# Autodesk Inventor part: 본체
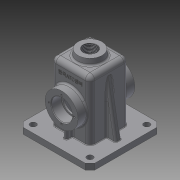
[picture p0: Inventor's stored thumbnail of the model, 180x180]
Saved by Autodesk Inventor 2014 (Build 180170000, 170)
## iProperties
Created: 2017-08
Part Number: 본체
Material: 일반
Document SubType Name: Modeling
Designer: user
Density: 1 g/cm^3
Appearance: 기본값
Author: user
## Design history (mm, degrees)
sketch "스케치1"
  geometry: L1 (-32.5, -32.5)-(32.5, -32.5); L2 (32.5, -32.5)-(32.5, 32.5); L3 (32.5, 32.5)-(-32.5, 32.5); L4 (-32.5, 32.5)-(-32.5, -32.5); L5 (-32.5, -32.5)-(32.5, 32.5); L6 (32.5, -32.5)-(-32.5, 32.5); 1 further point
  constraints: 12 end point, 2 midpoint, 2 parallel, 1 horizontal, 1 perpendicular
  dimensions: "d0" = 65 distance of L2.end L3.end; "d1" = 65 distance of L1.end L2.end
extrude "돌출1" new body sketch "스케치1" distance "d2" = 55; taper "d4" = 0 deg; dims "d3" = 55, "d5" = 0
feature "쉘1" dims "d6" = 5
sketch "스케치2"
  geometry: C1 r 27.5 at (32.5, -55); 1 further point
  constraints: 1 centre point, 1 coincident
  dimensions: "d7" = 55 diameter of C1
extrude "돌출2" join sketch "스케치2" distance "d8" = 15; taper "d9" = 0 deg
fillet "모깎기1" dims "d10" = 8
fillet "모깎기2" dims "d11" = 8
hole "구멍1" diameter "d14" = 30; stored, may be unused: countersink angle "d18" = 90 deg, drill point angle "d20" = 118 deg; dims "d12" = 10, "d13" = 10, "d15" = 6, "d16" = 35, "d17" = 17, "d19" = 8
fillet "모깎기3" dims "d21" = 3
fillet "모깎기4" dims "d22" = 3
sketch "스케치3"
  geometry: L1 (-32.5, 24.5)-(-32.5, -24.5) reference; L2 (-24.5, -32.5)-(24.5, -32.5) reference; L3 (32.5, -24.5)-(32.5, 24.5) reference; L4 (24.5, 32.5)-(-24.5, 32.5) reference; L5 (-60, 60)-(60, 60); L6 (60, 60)-(60, -60); L7 (60, -60)-(-60, -60); L8 (-60, -60)-(-60, 60); L9 (-60, 60)-(60, -60); L10 (60, 60)-(-60, -60); A1 r 8 centre (-24.5, 24.5) between (-24.5, 32.5) and (-32.5, 24.5) reference; A2 r 8 centre (-24.5, -24.5) between (-32.5, -24.5) and (-24.5, -32.5) reference; A3 r 8 centre (24.5, -24.5) between (24.5, -32.5) and (32.5, -24.5) reference; A4 r 8 centre (24.5, 24.5) between (32.5, 24.5) and (24.5, 32.5) reference; 1 further point
  constraints: 12 end point, 2 midpoint, 2 parallel, 1 horizontal, 1 perpendicular
  dimensions: "d23" = 120 distance of L5.start L5.end; "d24" = 120 distance of L7.end L5.start
extrude "돌출3" join sketch "스케치3" distance "d25" = 10; taper "d26" = 0 deg
node "작업 평면1"
sketch "스케치4"
  geometry: C1 r 20 at (0, 0); 1 further point
  constraints: 1 centre point, 1 coincident
  dimensions: "d28" = 40 diameter of C1
extrude "돌출4" join sketch "스케치4" stored distance "d29" = 10; taper "d30" = 0 deg
feature "면 기울기1" dims angle "d31" = 7 deg
hole "구멍2" diameter "d34" = 22.835; stored, may be unused: countersink angle "d38" = 90 deg, drill point angle "d40" = 118 deg; dims "d32" = 10, "d33" = 10, "d35" = 30, "d36" = 35, "d37" = 17, "d39" = 8
sketch "스케치5" dims "d41" = 42
  geometry: C1 r 17.5 at (0, 0) reference; C2 r 27.5 at (0, 0) reference; 2 further points
  constraints: 2 vertical alignment, 1 coincident, 2 other
hole "구멍3" sketch "스케치5" at (0, 21) diameter "d42" = 3.242; stored, may be unused: countersink angle "d46" = 90 deg, drill point angle "d48" = 118 deg; dims "d43" = 8, "d44" = 35, "d45" = 17, "d47" = 10
sketch "스케치6"
  geometry: L1 (60, -60)-(60, 60) reference; L2 (-47.5, -47.5)-(47.5, -47.5); 4 further points
  constraints: 2 coincident, 2 end point, 1 midpoint, 1 perpendicular, 1 vertical alignment
  dimensions: "d52" = 95 distance of L2.start L2.end; "d53" = 47.5 distance of point (0, 0) point (0, -47.5)
hole "구멍4" sketch "스케치6" at (-47.5, -47.5), (47.5, -47.5) diameter "d54" = 10; stored, may be unused: countersink angle "d58" = 90 deg, drill point angle "d60" = 118 deg; dims "d55" = 8, "d56" = 35, "d57" = 17, "d59" = 10
chamfer "모따기1" distance "d61" = 8; stored, may be unused: second distance "d62" = 2, angle "d63" = 45 deg
fillet "모깎기5" dims "d64" = 3
chamfer "모따기2" distance "d65" = 1; stored, may be unused: second distance "d66" = 2, angle "d67" = 45 deg
fillet "모깎기6" dims "d68" = 0.3
sketch "스케치7"
  geometry: L1 (-11.418, 65)-(-11.418, 50) reference; L2 (-11.418, 50)-(-24.5, 50) reference; L3 (-27.5, 47)-(-27.5, -55) reference; L4 (-27.5, -55)-(-60, -55) reference; L5 (-60, -55)-(-60, -45) reference; L6 (-60, -45)-(-32.5, -45) reference; L7 (-32.5, -45)-(-32.5, 47) reference; L8 (-24.5, 55)-(-23.882, 55) reference; L9 (-20.904, 57.634)-(-20, 65) reference; L10 (-20, 65)-(-11.418, 65) reference; L11 (11.418, 50)-(11.418, 65) reference; L12 (11.418, 65)-(20, 65) reference; L13 (20, 65)-(20.904, 57.634) reference; L14 (23.882, 55)-(24.5, 55) reference; L15 (32.5, 47)-(32.5, -45) reference; L16 (32.5, -45)-(60, -45) reference; L17 (60, -45)-(60, -55) reference; L18 (60, -55)-(27.5, -55) reference; L19 (27.5, -55)-(27.5, 47) reference; L20 (24.5, 50)-(11.418, 50) reference; L21 (-48, -45)-(-32.5, 42.905); A1 r 3 centre (-24.5, 47) between (-24.5, 50) and (-27.5, 47) reference; A2 r 8 centre (-24.5, 47) between (-24.5, 55) and (-32.5, 47) reference; A3 r 3 centre (-23.882, 58) between (-23.882, 55) and (-20.904, 57.634) reference; A4 r 3 centre (23.882, 58) between (20.904, 57.634) and (23.882, 55) reference; A5 r 8 centre (24.5, 47) between (32.5, 47) and (24.5, 55) reference; A6 r 3 centre (24.5, 47) between (27.5, 47) and (24.5, 50) reference; 1 further point
  constraints: 2 end point, 2 point on line
  dimensions: "d69" = 12 distance from line of L5 L21.start; "d70" = 100 deg angle of L6 L21
feature "리브1" sketch "스케치7" dims "d71" = 1, "d72" = 10, "d73" = 0, "d74" = 0, "d75" = 1, "d76" = 1
fillet "모깎기7" dims "d77" = 3
fillet "모깎기8" dims "d78" = 3
sketch "스케치8"
  geometry: L1 (-37.5, -22.621)-(-36.526, -21) reference; L2 (-36.526, -21)-(-37.5, -19.379) reference; L3 (-37.5, -19.379)-(-47.5, -19.379) reference; L4 (-47.5, -19.379)-(-47.5, -18.5) reference; L5 (-47.5, -18.5)-(-46.5, -17.5) reference; L6 (-46.5, -17.5)-(-30.8, -17.5) reference; L7 (-30.5, -17.2)-(-30.5, -15) reference; L8 (-30.5, -15)-(-27.5, -15) reference; L9 (-27.5, -15)-(-27.5, -55) reference; L10 (-27.5, -55)-(-60, -55) reference; L11 (-60, -55)-(-60, -45) reference; L12 (-60, -45)-(-32.5, -45) reference; L13 (-32.5, -45)-(-32.5, -30.5) reference; L14 (-35.5, -27.5)-(-47.5, -27.5) reference; L15 (-47.5, -27.5)-(-47.5, -22.621) reference; L16 (-47.5, -22.621)-(-37.5, -22.621) reference; L17 (32.5, -30.5)-(32.5, -45) reference; L18 (32.5, -45)-(60, -45) reference; L19 (60, -45)-(60, -55) reference; L20 (60, -55)-(27.5, -55) reference; L21 (27.5, -55)-(27.5, -15) reference; L22 (27.5, -15)-(30.5, -15) reference; L23 (30.5, -15)-(30.5, -17.2) reference; L24 (30.8, -17.5)-(46.5, -17.5) reference; L25 (46.5, -17.5)-(47.5, -18.5) reference; L26 (47.5, -18.5)-(47.5, -19.379) reference; L27 (47.5, -19.379)-(37.5, -19.379) reference; L28 (37.5, -19.379)-(36.526, -21) reference; L29 (36.526, -21)-(37.5, -22.621) reference; L30 (37.5, -22.621)-(47.5, -22.621) reference; L31 (47.5, -22.621)-(47.5, -27.5) reference; L32 (47.5, -27.5)-(35.5, -27.5) reference; L33 (35.5, 27.5)-(47.5, 27.5) reference; L34 (47.5, 27.5)-(47.5, 22.621) reference; L35 (47.5, 22.621)-(37.5, 22.621) reference; L36 (37.5, 22.621)-(36.526, 21) reference; L37 (36.526, 21)-(37.5, 19.379) reference; L38 (37.5, 19.379)-(47.5, 19.379) reference; L39 (47.5, 19.379)-(47.5, 18.5) reference; L40 (47.5, 18.5)-(46.5, 17.5) reference; L41 (46.5, 17.5)-(30.8, 17.5) reference; L42 (30.5, 17.2)-(30.5, 15) reference; L43 (30.5, 15)-(27.5, 15) reference; L44 (27.5, 15)-(27.5, 47) reference; L45 (24.5, 50)-(11.418, 50) reference; L46 (11.418, 50)-(11.418, 65) reference; L47 (11.418, 65)-(20, 65) reference; L48 (20, 65)-(20.904, 57.634) reference; L49 (23.882, 55)-(24.5, 55) reference; L50 (32.5, 47)-(32.5, 30.5) reference; L51 (-32.5, 30.5)-(-32.5, 47) reference; L52 (-24.5, 55)-(-23.882, 55) reference; L53 (-20.904, 57.634)-(-20, 65) reference; L54 (-20, 65)-(-11.418, 65) reference; L55 (-11.418, 65)-(-11.418, 50) reference; L56 (-11.418, 50)-(-24.5, 50) reference; L57 (-27.5, 47)-(-27.5, 15) reference; L58 (-27.5, 15)-(-30.5, 15) reference; L59 (-30.5, 15)-(-30.5, 17.2) reference; L60 (-30.8, 17.5)-(-46.5, 17.5) reference; L61 (-46.5, 17.5)-(-47.5, 18.5) reference; L62 (-47.5, 18.5)-(-47.5, 19.379) reference; L63 (-47.5, 19.379)-(-37.5, 19.379) reference; L64 (-37.5, 19.379)-(-36.526, 21) reference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; A1 r 0.3 centre (-30.8, -17.2) between (-30.8, -17.5) and (-30.5, -17.2) reference; A2 r 3 centre (-35.5, -30.5) between (-32.5, -30.5) and (-35.5, -27.5) reference; A3 r 3 centre (35.5, -30.5) between (35.5, -27.5) and (32.5, -30.5) reference; A4 r 0.3 centre (30.8, -17.2) between (30.5, -17.2) and (30.8, -17.5) reference; A5 r 3 centre (35.5, 30.5) between (32.5, 30.5) and (35.5, 27.5) reference; A6 r 0.3 centre (30.8, 17.2) between (30.8, 17.5) and (30.5, 17.2) reference; A7 r 3 centre (24.5, 47) between (27.5, 47) and (24.5, 50) reference; A8 r 3 centre (23.882, 58) between (20.904, 57.634) and (23.882, 55) reference; A9 r 8 centre (24.5, 47) between (32.5, 47) and (24.5, 55) reference; A10 r 3 centre (-35.5, 30.5) between (-35.5, 27.5) and (-32.5, 30.5) reference; A11 r 8 centre (-24.5, 47) between (-24.5, 55) and (-32.5, 47) reference; A12 r 3 centre (-23.882, 58) between (-23.882, 55) and (-20.904, 57.634) reference; A13 r 3 centre (-24.5, 47) between (-24.5, 50) and (-27.5, 47) reference; A14 r 0.3 centre (-30.8, 17.2) between (-30.5, 17.2) and (-30.8, 17.5) reference; 1 further point
  constraints: 2 end point, 2 point on line, 1 perpendicular
  dimensions: "d79" = 15 distance between parallel lines of L9 L69
feature "리브2" sketch "스케치8" dims "d80" = 1, "d81" = 6, "d82" = 0, "d83" = 0, "d84" = 1, "d85" = 1
fillet "모깎기9" dims "d86" = 3
fillet "모깎기10" dims "d87" = 3
fillet "모깎기11" dims "d88" = 1
sketch "스케치9"
  geometry: L1 (4.5, 18)-(44.5, 18) reference; L2 (-8, 0)-(-8, -91) reference; 1 further point
  constraints: 1 other
  dimensions: "d89" = 32.5 distance from line of L2 point (24.5, -8); "d90" = 26 distance from line of point (24.5, -8) L1
feature "엠보싱1" sketch "스케치9" dims "d91" = 0.5, "d92" = 0
node "솔리드1"
mirror "대칭1"
mirror "대칭2"
pattern_circular "원형 패턴1" dims angle "d50" = 360 deg
mirror "대칭3"
mirror "대칭4"
mirror "대칭5"
mirror "대칭6"
node "절단 모서리 투영1"
node "절단 모서리 투영2"
